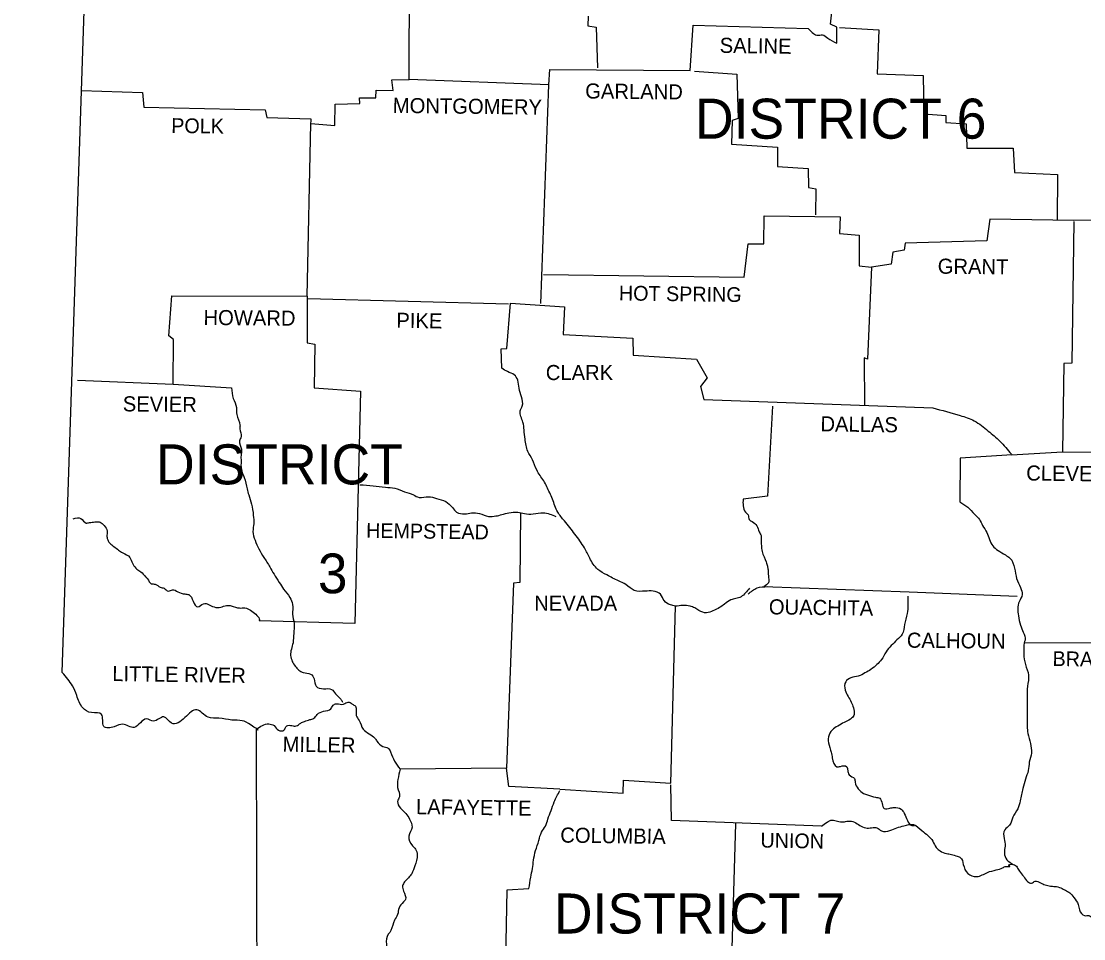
# Model space of a CAD drawing. Extents: x 1373884 to 1376992, y 1168426 to 1170473.
# Drawn here: x 1376295.6 to 1376598.2, y 1169768.1 to 1170029.4 of the extents above; entities that cross this region are included whole.
import ezdxf

# ---------------------------------------------------------------- set-up
doc = ezdxf.new("R2010")
doc.units = 0
doc.layers.add('R_Draft', color=7, linetype='Continuous')

msp = doc.modelspace()

# ---------------------------------------------------------------- linework, layer by layer
at = {"layer": 'R_Draft'}
for points in [[(1376307.29, 1169843.9), (1376316.29, 1170115.2), (1376295.59, 1170281.4)], [(1376311.59, 1169927.2), (1376338.89, 1169926), (1376338.99, 1169938.8), (1376337.59, 1169939.8), (1376338.49, 1169951.2), (1376376.99, 1169951.1), (1376378.09, 1170000.3), (1376384.89, 1169999.7), (1376384.99, 1170005.8), (1376391.99, 1170006), (1376391.89, 1170007.6), (1376396.59, 1170007.6), (1376396.69, 1170009.8), (1376401.49, 1170009.7), (1376401.09, 1170012.7), (1376406.09, 1170012.8), (1376406.29, 1170071.3)], [(1376527.89, 1170023.1), (1376527.89, 1170027.7), (1376526.09, 1170028.6), (1376526.79, 1170035.6), (1376539.09, 1170036.3), (1376539.49, 1170040.2), (1376552.59, 1170040.7), (1376552.29, 1170043.4), (1376559.49, 1170042.6)], [(1376457.09, 1170030.8), (1376456.99, 1170028.1), (1376459.29, 1170027.7), (1376459.69, 1170016.1)], [(1376445.89, 1170011.3), (1376446.09, 1170015.6), (1376486.09, 1170015.4), (1376486.99, 1170028.3), (1376519.69, 1170027.3)], [(1376528.59, 1170027.6), (1376539.79, 1170026.9), (1376539.39, 1170014.4), (1376552.49, 1170013.9), (1376552.69, 1170003), (1376558.89, 1170002.5), (1376558.89, 1170000.6), (1376564.69, 1170000.2), (1376564.89, 1169993.2), (1376578.09, 1169993.2), (1376578.49, 1169986.3), (1376590.69, 1169985.7), (1376590.59, 1169972.7)], [(1376487.29, 1170015.2), (1376499.39, 1170014.3), (1376499.79, 1170001.7), (1376498.09, 1170001.1), (1376497.89, 1169994.4), (1376510.99, 1169993.5), (1376510.99, 1169988), (1376519.69, 1169987.5), (1376519.79, 1169982), (1376521.89, 1169981.7), (1376521.79, 1169974.3)], [(1376445.89, 1170011.3), (1376406.09, 1170012.8)], [(1376443.59, 1169949), (1376445.89, 1170011.3)], [(1376312.79, 1170009.7), (1376330.09, 1170009.1), (1376330.49, 1170004.9), (1376365.09, 1170004.2), (1376365.49, 1170002), (1376378.09, 1170001.6), (1376377.99, 1169999.7)], [(1376709.89, 1169984.2), (1376672.09, 1169985.2), (1376671.89, 1169972.9), (1376595.39, 1169972.6)], [(1376444.29, 1169957.3), (1376501.49, 1169956.5), (1376502.59, 1169966), (1376507.09, 1169966), (1376507.19, 1169974), (1376528.79, 1169973.7), (1376528.59, 1169968.9), (1376534.19, 1169968.5), (1376534.19, 1169959.7), (1376537.79, 1169959.4)], [(1376595.39, 1169972.6), (1376571.49, 1169973), (1376570.59, 1169966.9), (1376547.29, 1169966.2), (1376547.09, 1169964.2), (1376543.79, 1169963.6), (1376543.39, 1169960.2), (1376537.79, 1169959.4)], [(1376595.39, 1169972.4), (1376594.79, 1169932), (1376592.49, 1169931.9), (1376592.19, 1169906.8)], [(1376537.79, 1169959.4), (1376536.59, 1169933.2), (1376535.69, 1169933.5), (1376535.79, 1169919.9)], [(1376376.99, 1169951.1), (1376376.99, 1169937.8), (1376379.19, 1169937.4), (1376378.99, 1169925), (1376392.19, 1169924), (1376390.59, 1169857.9), (1376363.39, 1169858.6)], [(1376377.19, 1169950.4), (1376434.39, 1169948.9)], [(1376432.49, 1169930.6), (1376432.29, 1169936.1), (1376433.89, 1169936.2), (1376434.89, 1169949.1), (1376450.29, 1169948.1), (1376449.89, 1169940.2), (1376469.79, 1169939.1), (1376469.89, 1169934.3), (1376487.89, 1169933.2), (1376490.99, 1169927.8), (1376489.09, 1169925.4), (1376489.99, 1169921.7), (1376555.19, 1169919.3)], [(1376338.89, 1169926), (1376355.49, 1169925)], [(1376509.59, 1169919.8), (1376508.09, 1169894.1), (1376501.19, 1169893.3)], [(1376577.79, 1169905.9), (1376562.99, 1169905), (1376562.89, 1169892.5)], [(1376577.59, 1169905.9), (1376592.19, 1169906.8)], [(1376592.19, 1169906.8), (1376627.59, 1169906.6)], [(1376437.79, 1169889.5), (1376437.59, 1169869.6), (1376435.79, 1169869.4), (1376433.79, 1169816.7)], [(1376507.09, 1169868.4), (1376548.49, 1169866.9), (1376579.19, 1169865.7)], [(1376448.99, 1169810.7), (1376466.99, 1169809.6), (1376467.09, 1169813.3), (1376480.59, 1169812.4), (1376481.89, 1169862.8)], [(1376581.19, 1169852.4), (1376626.39, 1169852.5)], [(1376729.29, 1169746.3), (1376362.79, 1169746.9), (1376362.59, 1169827.8)], [(1376448.99, 1169810.7), (1376434.49, 1169811.5), (1376433.79, 1169816.7), (1376403.49, 1169816.4)], [(1376523.49, 1169800.2), (1376480.79, 1169801.8), (1376480.59, 1169811.9)], [(1376498.99, 1169800.9), (1376497.39, 1169746)], [(1376433.29, 1169747.4), (1376433.99, 1169782), (1376440.19, 1169782.4)]]:
    msp.add_lwpolyline(points, dxfattribs=at)
for points in [[(1376519.69, 1170027.3), (1376520.89, 1170026.2), (1376522.19, 1170025.4), (1376523.79, 1170025.5), (1376525.29, 1170024.6), (1376527.89, 1170023.1)], [(1376481.89, 1169862.8), (1376480.49, 1169863.2), (1376478.69, 1169864.4), (1376477.69, 1169866.2), (1376475.59, 1169867.1), (1376473.29, 1169867.1), (1376470.19, 1169867.3), (1376467.79, 1169869), (1376465.69, 1169870), (1376462.39, 1169871.7), (1376459.79, 1169873.3), (1376457.49, 1169876.5), (1376455.99, 1169879.4), (1376453.29, 1169883.3), (1376450.29, 1169887.1), (1376448.39, 1169889.6), (1376446.89, 1169893.3), (1376446.09, 1169895.1), (1376444.39, 1169898.5), (1376442.39, 1169901.6), (1376441.19, 1169904.5), (1376439.89, 1169906.9), (1376439.09, 1169910.4), (1376438.79, 1169913), (1376438.49, 1169915.2), (1376437.69, 1169918.4), (1376438.29, 1169919.8), (1376438.09, 1169922.4), (1376437.39, 1169924.9), (1376436.99, 1169927.2), (1376435.99, 1169928.7), (1376434.09, 1169929.6), (1376432.49, 1169930.6)], [(1376355.49, 1169925), (1376355.99, 1169922), (1376356.89, 1169919.4), (1376356.99, 1169917.4), (1376357.89, 1169914.4), (1376357.89, 1169913.3), (1376358.19, 1169911.1), (1376357.79, 1169909.9), (1376358.29, 1169907.5), (1376358.19, 1169905.7), (1376358.19, 1169904.2), (1376358.29, 1169901.7), (1376359.09, 1169899.5), (1376359.89, 1169896.2), (1376360.39, 1169894.5), (1376361.19, 1169891.9), (1376361.69, 1169888.7), (1376361.79, 1169886.3), (1376361.59, 1169884.1), (1376362.19, 1169881.6), (1376363.29, 1169879.1), (1376364.69, 1169876.7), (1376366.39, 1169874), (1376367.59, 1169871.9), (1376369.09, 1169869.6), (1376370.29, 1169867.7), (1376372.09, 1169865.3), (1376372.89, 1169863.3), (1376372.89, 1169860.5), (1376373.29, 1169857.9), (1376373.19, 1169855), (1376372.99, 1169852.4), (1376372.29, 1169848.8), (1376372.79, 1169847.1), (1376374.69, 1169844.6), (1376375.89, 1169843.9), (1376377.99, 1169843.5), (1376378.99, 1169842.1), (1376379.59, 1169840), (1376381.69, 1169839.3), (1376383.99, 1169839.1), (1376385.09, 1169837.9), (1376386.59, 1169836.3), (1376387.09, 1169835.5)], [(1376555.19, 1169919.3), (1376562.99, 1169917.1), (1376566.99, 1169915.6), (1376570.99, 1169912.7), (1376574.29, 1169909.8), (1376577.59, 1169906.1)], [(1376391.99, 1169897.4), (1376395.79, 1169897.1), (1376399.29, 1169896.7), (1376401.99, 1169896.4), (1376404.79, 1169895.4), (1376407.29, 1169894.5), (1376408.89, 1169893.8), (1376411.59, 1169894), (1376413.89, 1169893.5), (1376416.49, 1169892.6), (1376418.39, 1169890.9), (1376419.59, 1169889.6), (1376421.89, 1169889.1), (1376423.79, 1169889.4), (1376426.09, 1169889.2), (1376428.69, 1169888.4), (1376430.79, 1169888.5), (1376432.49, 1169888.9), (1376434.49, 1169889.4), (1376436.99, 1169889.6), (1376438.89, 1169889.2), (1376441.39, 1169889.1), (1376444.29, 1169889.4), (1376447.89, 1169888.4)], [(1376501.19, 1169893.3), (1376501.19, 1169891.4), (1376501.89, 1169889.6), (1376502.59, 1169888.8), (1376502.89, 1169887.5), (1376503.79, 1169886.9), (1376505.09, 1169885.7), (1376505.79, 1169884), (1376506.29, 1169882.9), (1376506.29, 1169881.5), (1376506.39, 1169880.1), (1376506.59, 1169878.4), (1376507.79, 1169875.4), (1376508.09, 1169874.2), (1376508.29, 1169873.2), (1376508.39, 1169871.5), (1376508.39, 1169869.5), (1376507.09, 1169868.4)], [(1376562.89, 1169892.5), (1376565.19, 1169891), (1376567.09, 1169889), (1376568.49, 1169887.5), (1376569.39, 1169885.8), (1376570.59, 1169883.8), (1376572.29, 1169880), (1376573.79, 1169878.7), (1376575.89, 1169877.4), (1376577.19, 1169876.5), (1376578.49, 1169873.6), (1376579.09, 1169870.7), (1376580.19, 1169868.1), (1376580.69, 1169866.1), (1376579.79, 1169864.1), (1376579.59, 1169860.1), (1376580.19, 1169857.4), (1376580.99, 1169855.4), (1376581.49, 1169853.1), (1376581.19, 1169852.4)], [(1376310.39, 1169887.7), (1376312.59, 1169887.8), (1376314.09, 1169886.5), (1376314.99, 1169886.6), (1376316.59, 1169886.8), (1376318.09, 1169886.7), (1376319.19, 1169885.8), (1376320.09, 1169884.2), (1376319.99, 1169882.7), (1376320.09, 1169882.1), (1376320.79, 1169880.8), (1376321.99, 1169879.8), (1376323.29, 1169878.8), (1376324.49, 1169878), (1376326.49, 1169876.7), (1376326.69, 1169876.3), (1376327.49, 1169874.7), (1376328.49, 1169873.4), (1376329.69, 1169872.6), (1376330.99, 1169871.2), (1376331.59, 1169870.6), (1376332.59, 1169869.2), (1376333.69, 1169869.1), (1376335.19, 1169868.2), (1376336.29, 1169867.9), (1376337.49, 1169867.1), (1376338.69, 1169867.5), (1376340.19, 1169866.9), (1376342.19, 1169866.3), (1376343.29, 1169866.1), (1376344.59, 1169864.2), (1376345.89, 1169862.6), (1376347.49, 1169863.5), (1376350.49, 1169862.6), (1376352.39, 1169862.5), (1376354.09, 1169863), (1376355.39, 1169862.9), (1376357.79, 1169862.3), (1376359.29, 1169862.3), (1376360.89, 1169861.7), (1376362.39, 1169860.5), (1376363.39, 1169859.2), (1376363.39, 1169858.6)], [(1376502.99, 1169867.9), (1376501.89, 1169866.6), (1376500.59, 1169865.5), (1376499.09, 1169865), (1376497.69, 1169864.6), (1376495.89, 1169863.4), (1376494.49, 1169862.4), (1376492.59, 1169861.5), (1376490.79, 1169860.9), (1376488.59, 1169861.6), (1376487.39, 1169862.3), (1376486.09, 1169862.8), (1376481.89, 1169862.8)], [(1376502.59, 1169866.3), (1376505.19, 1169868), (1376508.09, 1169868.4)], [(1376548.09, 1169865.7), (1376547.89, 1169860.7), (1376547.19, 1169857.6), (1376546.49, 1169854.8), (1376544.99, 1169853.2), (1376543.39, 1169851.6), (1376541.89, 1169849.8), (1376540.59, 1169847.6), (1376539.29, 1169846.2), (1376537.59, 1169844.8), (1376535.89, 1169843.8), (1376533.99, 1169842.9), (1376531.89, 1169842.4), (1376530.39, 1169841.3), (1376530.29, 1169838.9), (1376531.99, 1169835.5), (1376532.59, 1169833.9), (1376532.79, 1169832), (1376532.09, 1169830.9), (1376530.49, 1169830), (1376528.59, 1169828.9), (1376526.89, 1169827.9), (1376525.69, 1169826.2), (1376525.49, 1169823.9), (1376526.29, 1169821.2), (1376526.59, 1169819.6), (1376527.89, 1169817.1), (1376528.89, 1169817.2), (1376530.69, 1169817.1), (1376530.89, 1169816.6), (1376530.99, 1169816.1), (1376531.39, 1169814.8), (1376532.89, 1169813.7), (1376533.09, 1169812.7), (1376533.99, 1169810.8), (1376535.49, 1169809.5), (1376536.59, 1169809.1), (1376538.89, 1169808.4), (1376540.09, 1169808.1), (1376541.39, 1169805.2), (1376542.99, 1169805.3), (1376544.19, 1169805.5), (1376546.19, 1169805), (1376547.09, 1169803.8), (1376547.99, 1169801.8), (1376549.19, 1169800.4), (1376549.99, 1169800.4)], [(1376581.19, 1169852.4), (1376581.59, 1169846.2), (1376582.49, 1169843.2), (1376582.19, 1169840), (1376582.09, 1169836.9), (1376582.09, 1169834.1), (1376582.09, 1169831.4), (1376582.09, 1169828.6), (1376582.29, 1169826.6), (1376582.99, 1169823.7), (1376583.29, 1169821), (1376582.69, 1169818.4), (1376582.39, 1169816), (1376581.59, 1169813.6), (1376580.89, 1169810.9), (1376580.09, 1169807.4), (1376579.39, 1169805.1), (1376577.99, 1169802.7), (1376577.09, 1169800.5), (1376575.69, 1169799.1), (1376575.49, 1169796.7), (1376575.79, 1169794.5), (1376575.59, 1169792.5), (1376576.29, 1169790.6), (1376578.09, 1169789.3)], [(1376362.59, 1169827.8), (1376362.99, 1169827.6), (1376361.09, 1169828.9), (1376358.49, 1169830.2), (1376355.59, 1169830.4), (1376351.89, 1169830.9), (1376348.79, 1169831.2), (1376345.59, 1169833.3), (1376342.19, 1169831.1), (1376338.39, 1169829.5), (1376336.19, 1169831.3), (1376333.29, 1169830.1), (1376331.29, 1169830.7), (1376327.79, 1169828.3), (1376324.49, 1169829.2), (1376322.09, 1169828.5), (1376319.09, 1169828.6), (1376318.49, 1169832), (1376315.59, 1169832.5), (1376313.09, 1169833.9), (1376311.39, 1169837.4), (1376310.19, 1169840.1), (1376307.29, 1169843.9)], [(1376362.59, 1169827.8), (1376366.09, 1169829.3), (1376367.59, 1169828.8), (1376368.89, 1169827.5), (1376370.39, 1169827.5), (1376371.19, 1169828.7), (1376372.69, 1169828.8), (1376373.89, 1169828.7), (1376375.19, 1169829.5), (1376376.29, 1169830), (1376377.79, 1169830.5), (1376378.89, 1169830.9), (1376379.89, 1169832), (1376381.69, 1169832.9), (1376383.79, 1169833.6), (1376384.39, 1169834.6), (1376385.39, 1169835), (1376387.39, 1169834.9), (1376388.69, 1169835.5), (1376389.79, 1169835), (1376390.79, 1169834.3), (1376390.99, 1169831.7), (1376391.79, 1169830.3), (1376392.99, 1169827.8), (1376394.69, 1169826.5), (1376396.29, 1169825.2), (1376396.89, 1169824.4), (1376398.59, 1169822.9), (1376400.09, 1169822.4), (1376400.79, 1169821.3), (1376401.89, 1169818.7), (1376403.49, 1169816.4)], [(1376403.49, 1169816.4), (1376402.89, 1169813.5), (1376402.79, 1169811.2), (1376403.29, 1169808.5), (1376402.79, 1169807.2), (1376403.59, 1169805.3), (1376405.09, 1169803.8), (1376406.19, 1169802.2), (1376406.89, 1169799.9), (1376405.99, 1169797.3), (1376406.99, 1169794.6), (1376407.89, 1169793.6), (1376408.39, 1169792), (1376407.69, 1169788.9), (1376406.79, 1169786.6), (1376404.79, 1169784.3), (1376404.19, 1169783.2), (1376404.49, 1169781.7), (1376404.99, 1169779.3), (1376404.49, 1169778.6), (1376403.19, 1169776.9), (1376402.79, 1169775), (1376401.89, 1169773.4), (1376400.89, 1169770.5), (1376399.59, 1169768.1), (1376399.39, 1169765.4), (1376397.39, 1169765.4), (1376395.09, 1169765.4), (1376392.99, 1169763.9), (1376391.09, 1169763.8), (1376388.79, 1169762.9), (1376387.39, 1169761), (1376386.89, 1169758.9), (1376386.29, 1169756.9), (1376386.89, 1169753.5), (1376387.79, 1169751.1), (1376388.49, 1169749.2), (1376389.69, 1169746.1)], [(1376440.19, 1169782.4), (1376440.69, 1169785.6), (1376441.19, 1169788.1), (1376441.49, 1169790.5), (1376442.09, 1169793.2), (1376442.99, 1169796.1), (1376443.79, 1169798.5), (1376444.89, 1169800.2), (1376445.59, 1169802.2), (1376446.49, 1169804.6), (1376447.39, 1169807.1), (1376448.99, 1169810.3)], [(1376523.49, 1169800.2), (1376525.09, 1169801.3), (1376526.59, 1169801.9), (1376528.09, 1169801.6), (1376529.69, 1169801.4), (1376531.09, 1169801.6), (1376532.89, 1169801.3), (1376534.39, 1169800.4), (1376536.09, 1169799.7), (1376537.79, 1169799.7), (1376539.29, 1169799.7), (1376540.59, 1169798.8), (1376542.99, 1169798.9), (1376544.99, 1169799.7), (1376546.99, 1169800.3), (1376549.69, 1169800.6), (1376552.09, 1169798.9), (1376553.79, 1169797.5), (1376555.19, 1169795.9), (1376556.19, 1169794.1), (1376557.29, 1169793.1), (1376559.09, 1169792.4), (1376560.49, 1169792.1), (1376562.19, 1169791.6), (1376563.09, 1169791.2), (1376563.89, 1169789.3), (1376565.19, 1169786.7), (1376567.69, 1169785.8), (1376570.79, 1169787), (1376573.29, 1169787.7), (1376575.09, 1169788.3), (1376576.19, 1169788.7), (1376577.19, 1169788.8), (1376576.89, 1169789), (1376578.09, 1169789.3), (1376579.19, 1169788.5), (1376579.89, 1169787.4), (1376581.09, 1169785.8), (1376582.19, 1169784.4), (1376583.29, 1169783.9), (1376584.39, 1169784.5), (1376585.89, 1169784), (1376587.19, 1169783.5), (1376588.69, 1169783.1), (1376589.99, 1169783), (1376591.69, 1169782.6), (1376592.99, 1169781.9), (1376594.19, 1169781.2), (1376595.39, 1169779.9), (1376596.59, 1169777.9), (1376596.99, 1169776.3), (1376598.39, 1169774.7), (1376599.69, 1169774.7), (1376601.59, 1169772.1), (1376602.29, 1169771.1), (1376603.79, 1169769.3), (1376604.89, 1169769.3), (1376606.99, 1169768.9)]]:
    msp.add_spline(points, degree=3, dxfattribs=at)

# ---------------------------------------------------------------- texts
for s, height, rotation, p in [('SALINE', 4.301, 359.1491, (1376494.49, 1170020.4)), ('GARLAND', 4.301, 359.3658, (1376456.19, 1170007.4)), ('MONTGOMERY', 4.301, 359.2944, (1376401.39, 1170003.3)), ('POLK', 4.199, 359.2152, (1376338.29, 1169997.6)), ('GRANT', 4.301, 359.4032, (1376556.59, 1169957.5)), ('HOT SPRING', 4.201, 359.2216, (1376465.79, 1169949.9)), ('HOWARD', 4.301, 359.5145, (1376347.49, 1169942.9)), ('PIKE', 4.3, 359.0452, (1376402.39, 1169942.1)), ('SEVIER', 4.301, 359.4271, (1376324.49, 1169918.3)), ('DALLAS', 4.3, 359.2462, (1376523.19, 1169912.6)), ('CLEVELAND', 4.301, 359.3376, (1376581.79, 1169898.6)), ('HEMPSTEAD', 4.199, 359.1885, (1376393.79, 1169882.3)), ('OUACHITA', 4.301, 359.2043, (1376508.49, 1169860.5)), ('CALHOUN', 4.301, 359.3634, (1376547.79, 1169851)), ('BRADLEY', 4.199, 359.1449, (1376589.29, 1169845.8)), ('LITTLE RIVER', 4.3008, 359.1697, (1376321.49, 1169841.5)), ('MILLER', 4.3, 359.1319, (1376369.99, 1169821.4)), ('LAFAYETTE', 4.3, 359.1839, (1376407.99, 1169803.6)), ('COLUMBIA', 4.3, 359.2125, (1376449.09, 1169795.5)), ('UNION', 4.201, 358.9584, (1376506.09, 1169794.1))]:
    msp.add_text(s, height=height, rotation=rotation, dxfattribs=at).set_placement(p)
for s, height, p in [('DISTRICT 6', 11.4, (1376487.48, 1169995.94)), ('CLARK', 4.3, (1376444.99, 1169927.2)), ('DISTRICT', 11.4, (1376333.99, 1169897.5)), ('3', 11.3, (1376380.09, 1169866.5)), ('NEVADA', 4.3, (1376441.69, 1169861.5)), ('DISTRICT 7', 11.4, (1376447.29, 1169769.6))]:
    msp.add_text(s, height=height, dxfattribs=at).set_placement(p)

doc.saveas('drawing.dxf')
